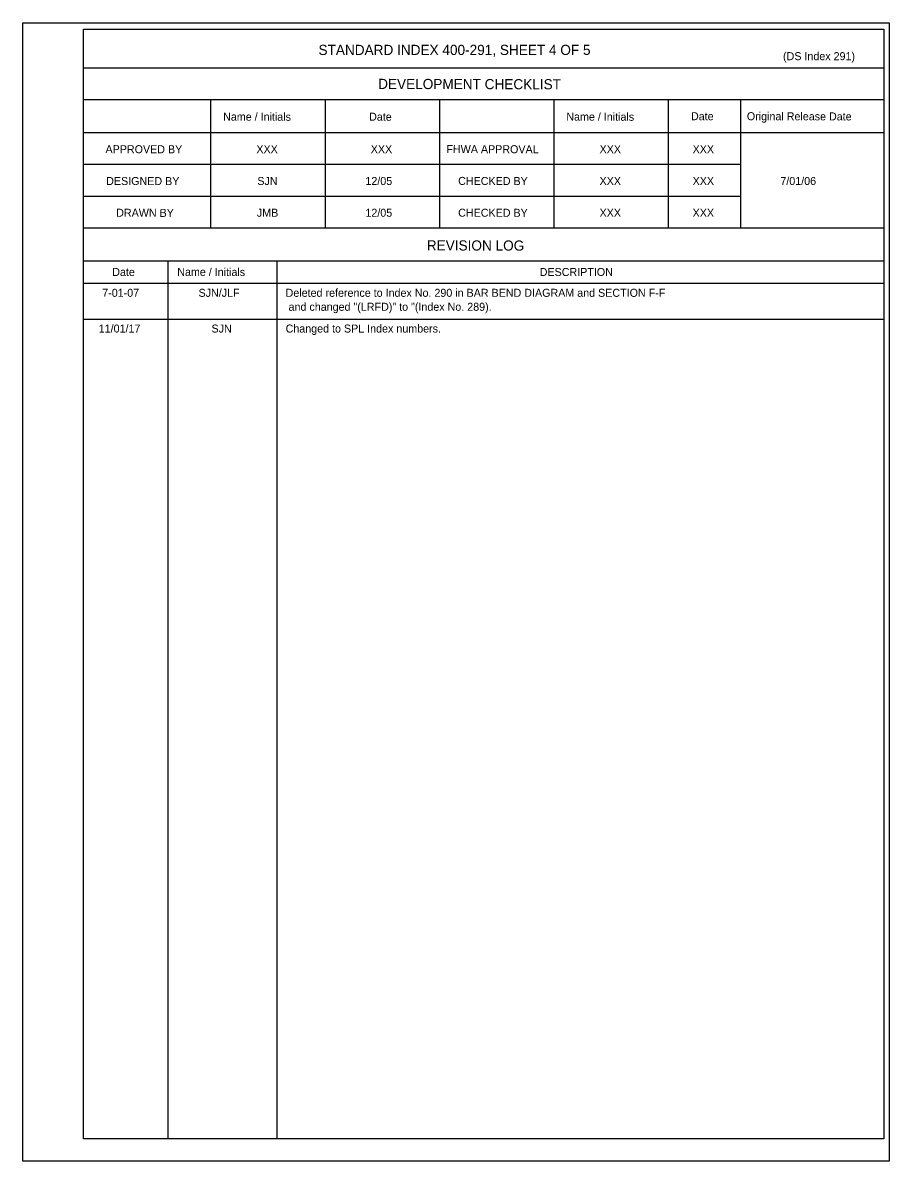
# Model space of a CAD drawing. Extents: x 10605.2 to 10672.7, y 76423.8 to 76450.2.
# Drawn here: x 10656.31 to 10672.67, y 76426.36 to 76447.86 of the extents above; entities that cross this region are included whole.
import ezdxf

# ---------------------------------------------------------------- set-up
doc = ezdxf.new("R2010")
doc.units = 0
for name, color, linetype in [('Border', 7, 'Continuous'), ('PlotBorder_dp', 7, 'Continuous'), ('SheetBorder_dp', 7, 'Continuous')]:
    doc.layers.add(name, color=color, linetype=linetype)

msp = doc.modelspace()

# ---------------------------------------------------------------- linework, layer by layer
at = {"layer": 'Border'}
for p, q in [((10672.567, 76447.007), (10657.457, 76447.007)), ((10672.567, 76446.407), (10657.457, 76446.407)), ((10659.857, 76446.407), (10659.857, 76443.986)), ((10662.017, 76446.407), (10662.017, 76443.986)), ((10664.177, 76446.407), (10664.177, 76443.986)), ((10666.337, 76446.407), (10666.337, 76443.986)), ((10668.497, 76446.407), (10668.497, 76443.986)), ((10669.858, 76446.407), (10669.858, 76443.986)), ((10672.567, 76445.786), (10657.457, 76445.786)), ((10669.858, 76445.186), (10657.457, 76445.186)), ((10669.858, 76444.586), (10657.457, 76444.586)), ((10672.567, 76443.986), (10657.457, 76443.986)), ((10672.567, 76443.365), (10657.457, 76443.365)), ((10659.047, 76443.365), (10659.047, 76426.785)), ((10661.104, 76443.365), (10661.104, 76426.785)), ((10672.567, 76442.942), (10657.457, 76442.942))]:
    msp.add_line(p, q, dxfattribs=at)
msp.add_lwpolyline([(10657.457, 76447.742), (10672.567, 76447.742), (10672.567, 76426.785), (10657.457, 76426.785)], close=True, dxfattribs=at)
at = {"layer": 'PlotBorder_dp'}
msp.add_line((10656.309, 76426.364), (10656.309, 76426.364), dxfattribs=at)
msp.add_lwpolyline([(10656.309, 76447.864), (10672.669, 76447.864), (10672.669, 76426.364), (10656.309, 76426.364)], close=True, dxfattribs=at)
at = {"layer": 'SheetBorder_dp'}
msp.add_line((10657.457, 76442.267), (10672.567, 76442.267), dxfattribs=at)

# ---------------------------------------------------------------- texts
for s, height, p in [('STANDARD INDEX 400-291, SHEET 4 OF 5', 0.192, (10661.893, 76447.256)), ('(DS Index 291)', 0.1512, (10670.664, 76447.158)), ('XXX', 0.1512, (10660.72, 76445.401)), ('XXX', 0.1512, (10662.88, 76445.401)), ('XXX', 0.1512, (10667.2, 76445.401)), ('XXX', 0.1512, (10668.957, 76445.401)), ('SJN', 0.1512, (10660.738, 76444.801)), ('12/05', 0.1512, (10662.779, 76444.801)), ('XXX', 0.1512, (10667.2, 76444.801)), ('XXX', 0.1512, (10668.957, 76444.801)), ('7/01/06', 0.1512, (10670.614, 76444.801)), ('JMB', 0.1512, (10660.729, 76444.201)), ('12/05', 0.1512, (10662.779, 76444.201)), ('XXX', 0.1512, (10667.2, 76444.201)), ('XXX', 0.1512, (10668.957, 76444.201)), ('DESCRIPTION', 0.1512, (10666.07, 76443.082)), ('7-01-07', 0.1512, (10657.81, 76442.689)), ('SJN/JLF', 0.1512, (10659.628, 76442.689)), ('Deleted reference to Index No. 290 in BAR BEND DIAGRAM and SECTION F-F ', 0.1512, (10661.272, 76442.689)), (' and changed "(LRFD)" to "(Index No. 289).', 0.1512, (10661.272, 76442.425)), ('11/01/17', 0.1512, (10657.743, 76442.014)), ('SJN', 0.1512, (10659.873, 76442.014)), ('Changed to SPL Index numbers.', 0.1512, (10661.272, 76442.014))]:
    msp.add_text(s, height=height, dxfattribs=at).set_placement(p)
for s, height, p in [('DEVELOPMENT CHECKLIST', 0.192, (10663.019, 76446.614)), ('Name / Initials', 0.1512, (10660.092, 76446.016)), ('Date', 0.1512, (10662.848, 76446.015)), ('Name / Initials', 0.1512, (10666.572, 76446.016)), ('Date', 0.1512, (10668.926, 76446.024)), ('Original Release Date', 0.1512, (10669.981, 76446.024)), ('APPROVED BY', 0.1512, (10657.871, 76445.402)), ('FHWA APPROVAL', 0.1512, (10664.308, 76445.403)), ('DESIGNED BY', 0.1512, (10657.884, 76444.801)), ('CHECKED BY', 0.1512, (10664.53, 76444.802)), ('DRAWN BY', 0.1512, (10658.073, 76444.201)), ('CHECKED BY', 0.1512, (10664.53, 76444.202)), ('REVISION LOG', 0.192, (10663.938, 76443.565)), ('Date', 0.1512, (10657.999, 76443.083)), ('Name / Initials', 0.1512, (10659.226, 76443.084))]:
    msp.add_text(s, height=height, rotation=359.8756, dxfattribs=at).set_placement(p)

doc.saveas('drawing.dxf')
